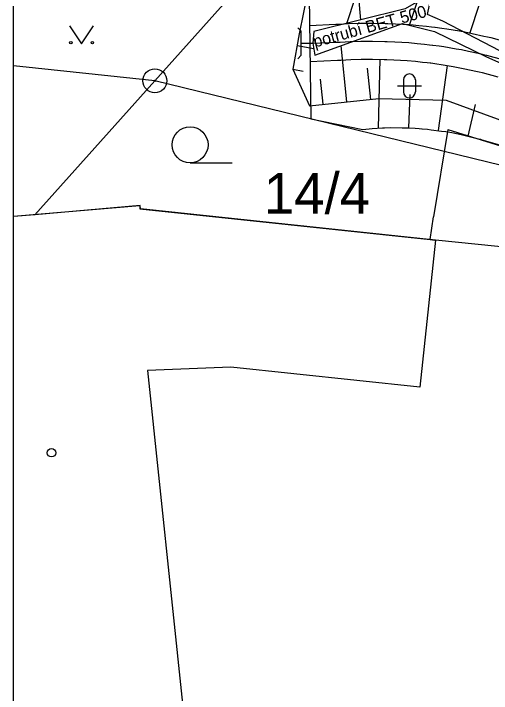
# Model space of a CAD drawing. Extents: x -564037 to -563722, y -1163561 to -1163412.
# Drawn here: x -564036.51 to -564016.6, y -1163474.68 to -1163446.37 of the extents above; entities that cross this region are included whole.
import ezdxf

# ---------------------------------------------------------------- set-up
doc = ezdxf.new("R2010")
doc.units = 0
for name, color, linetype in [('1', 7, 'Continuous'), ('Definiční body', 7, 'Continuous'), ('Hranice parcel', 7, 'Continuous'), ('Line', 7, 'Continuous'), ('Parcelní čísla', 7, 'Continuous'), ('Vnitřní kresba', 7, 'Continuous'), ('Vrstva 14', 7, 'Continuous'), ('Vrstva 20', 7, 'Continuous'), ('Vrstva 25', 7, 'Continuous'), ('Vrstva 41', 7, 'Continuous'), ('Vrstva 48', 7, 'Continuous'), ('Značky bodu BP', 7, 'Continuous'), ('Značky budov', 7, 'Continuous'), ('Značky kultur', 7, 'Continuous')]:
    doc.layers.add(name, color=color, linetype=linetype)

msp = doc.modelspace()

# ---------------------------------------------------------------- linework, layer by layer
for points in [[(-564024.219, -1163443.623), (-564024.118, -1163450.759), (-564021.959, -1163451.195), (-564021.563, -1163451.158), (-564021.141, -1163451.131), (-564021.053, -1163451.127), (-564020.798, -1163451.118), (-564020.319, -1163451.123), (-564020.03, -1163451.134), (-564019.77, -1163451.149), (-564019.605, -1163451.16), (-564019.496, -1163451.169), (-564019.485, -1163451.17), (-564019.482, -1163451.17), (-564019.263, -1163451.191), (-564019.103, -1163451.208), (-564018.675, -1163451.262), (-564018.499, -1163451.288), (-564018.254, -1163451.33), (-564017.862, -1163451.409), (-564017.742, -1163451.435), (-564017.633, -1163451.46), (-564017.074, -1163451.6), (-564017.058, -1163451.604), (-564016.993, -1163451.622), (-564016.265, -1163451.842)], [(-564024.173, -1163446.865), (-564023.075, -1163446.816), (-564022.934, -1163446.81), (-564022.523, -1163446.791), (-564022.059, -1163446.776), (-564021.555, -1163446.77), (-564021.021, -1163446.778), (-564020.91, -1163446.782), (-564020.588, -1163446.795), (-564019.985, -1163446.833), (-564019.623, -1163446.864), (-564019.297, -1163446.898), (-564019.09, -1163446.922), (-564018.953, -1163446.939), (-564018.939, -1163446.941), (-564018.937, -1163446.941), (-564018.662, -1163446.978), (-564018.462, -1163447.008), (-564017.928, -1163447.096), (-564017.708, -1163447.137), (-564017.402, -1163447.198), (-564016.912, -1163447.305), (-564016.761, -1163447.341), (-564016.625, -1163447.374), (-564015.927, -1163447.559)], [(-564024.04, -1163447.61), (-564023.041, -1163447.565), (-564022.901, -1163447.559), (-564022.489, -1163447.54), (-564022.042, -1163447.525), (-564021.557, -1163447.52), (-564021.042, -1163447.528), (-564020.935, -1163447.531), (-564020.624, -1163447.544), (-564020.043, -1163447.58), (-564019.694, -1163447.611), (-564019.38, -1163447.643), (-564019.18, -1163447.666), (-564019.049, -1163447.683), (-564019.035, -1163447.685), (-564019.033, -1163447.685), (-564018.768, -1163447.721), (-564018.575, -1163447.749), (-564018.06, -1163447.835), (-564017.848, -1163447.874), (-564017.553, -1163447.932), (-564017.081, -1163448.036), (-564016.936, -1163448.07), (-564016.805, -1163448.102), (-564016.131, -1163448.28)], [(-564024.152, -1163448.366), (-564023.007, -1163448.314), (-564022.867, -1163448.308), (-564022.456, -1163448.29), (-564022.025, -1163448.275), (-564021.558, -1163448.27), (-564021.063, -1163448.278), (-564020.96, -1163448.281), (-564020.661, -1163448.293), (-564020.102, -1163448.328), (-564019.765, -1163448.357), (-564019.463, -1163448.388), (-564019.271, -1163448.411), (-564019.144, -1163448.427), (-564019.131, -1163448.428), (-564019.129, -1163448.429), (-564018.874, -1163448.463), (-564018.688, -1163448.491), (-564018.193, -1163448.573), (-564017.988, -1163448.611), (-564017.705, -1163448.667), (-564017.25, -1163448.766), (-564017.111, -1163448.799), (-564016.984, -1163448.83), (-564016.336, -1163449.002)]]:
    msp.add_lwpolyline(points)
at = {"layer": '1'}
msp.add_lwpolyline([(-564036.505, -1163412.494), (-563721.505, -1163412.494), (-563721.505, -1163560.994), (-564036.505, -1163560.994)], close=True, dxfattribs=at)
at = {"layer": 'Definiční body'}
msp.add_lwpolyline([(-564018.41, -1163451.2), (-564019.01, -1163454.84)], dxfattribs=at)
at = {"layer": 'Hranice parcel'}
for p, q in [((-564030.62, -1163449.17), (-564025.34, -1163443.25)), ((-564035.62, -1163454.75), (-564030.62, -1163449.17)), ((-564035.62, -1163454.75), (-564036.505, -1163454.828))]:
    msp.add_line(p, q, dxfattribs=at)
for points in [[(-564030.62, -1163449.17), (-564036.505, -1163448.55)], [(-563988.32, -1163461.72), (-564001.74, -1163456.23), (-564030.62, -1163449.17)], [(-564018.93, -1163455.81), (-564031.22, -1163454.5), (-564031.23, -1163454.37), (-564035.62, -1163454.75)], [(-563996.99, -1163459.6), (-564013.06, -1163456.4), (-564018.93, -1163455.81)]]:
    msp.add_lwpolyline(points, dxfattribs=at)
at = {"layer": 'Line'}
for p, q in [((-564021.847, -1163444.413), (-564022.64, -1163446.796)), ((-564019.475, -1163445.202), (-564020.017, -1163446.831)), ((-564017.103, -1163445.992), (-564017.498, -1163447.179)), ((-564021.301, -1163451.142), (-564021.238, -1163448.275)), ((-564018.807, -1163451.245), (-564018.434, -1163448.533)), ((-564019.994, -1163449.738), (-564020.052, -1163451.133)), ((-564017.273, -1163450.154), (-564017.579, -1163451.474))]:
    msp.add_line(p, q, dxfattribs=at)
at = {"layer": 'Vnitřní kresba'}
msp.add_line((-564030.92, -1163461.24), (-564029.42, -1163475.59), dxfattribs=at)
msp.add_lwpolyline([(-564018.93, -1163455.81), (-564019.58, -1163461.93), (-564027.45, -1163461.09), (-564030.92, -1163461.24)], dxfattribs=at)
at = {"layer": 'Vrstva 14'}
for points in [[(-564007.48, -1163451.56), (-564015.37, -1163448.38), (-564016.56, -1163447.76), (-564018.62, -1163446.69), (-564019.26, -1163446.41), (-564019.18, -1163446.01), (-564017.7, -1163444.08)], [(-564018.38, -1163444.22), (-564019.25, -1163445.51), (-564019.73, -1163445.91), (-564020.19, -1163446.17), (-564024, -1163447.12)], [(-564021.14, -1163444.81), (-564023.19, -1163444.97), (-564024.24, -1163445.43), (-564024.61, -1163447.21), (-564024.87, -1163448.69), (-564024.18, -1163450.21), (-564021.29, -1163449.91), (-564018.48, -1163449.97), (-564014.8, -1163451.33), (-564012.14, -1163452.66), (-564006.89, -1163454.96)], [(-564023.95, -1163448.11), (-564020.3, -1163446.78), (-564018.97, -1163447.12), (-564016.8, -1163448.17), (-564015.46, -1163448.77), (-564007.72, -1163452.04)], [(-564024, -1163447.12), (-564024.04, -1163447.61), (-564023.95, -1163448.11)], [(-564018.41, -1163451.2), (-564015.23, -1163452.19), (-564012.52, -1163453.4), (-564007.28, -1163455.88), (-563999.25, -1163459.72), (-563994.12, -1163462.21), (-563988.58, -1163464.9), (-563990.48, -1163473.96), (-563991.73, -1163479.99), (-563994.29, -1163491.84), (-564004.63, -1163491.62)], [(-564019.15, -1163455.78), (-564019.01, -1163454.84)]]:
    msp.add_lwpolyline(points, dxfattribs=at)
at = {"layer": 'Vrstva 20'}
for p, q in [((-564024.669, -1163446.969), (-564024.528, -1163447.11)), ((-564024.528, -1163448.11), (-564024.528, -1163447.11)), ((-564024.528, -1163447.61), (-564024.04, -1163447.61)), ((-564024.669, -1163448.251), (-564024.528, -1163448.11))]:
    msp.add_line(p, q, dxfattribs=at)
at = {"layer": 'Vrstva 25'}
for p, q in [((-564020.266, -1163449.136), (-564020.266, -1163449.636)), ((-564019.766, -1163449.136), (-564019.766, -1163449.636)), ((-564020.516, -1163449.386), (-564019.516, -1163449.386))]:
    msp.add_line(p, q, dxfattribs=at)
msp.add_lwpolyline([(-564034.17, -1163446.88), (-564033.67, -1163447.63), (-564033.17, -1163446.88)], dxfattribs=at)
for centre in [(-564034.12, -1163447.58), (-564033.221, -1163447.58)]:
    msp.add_circle(centre, 0.05, dxfattribs=at)
for centre, start, end in [((-564020.016, -1163449.136), 0, 180), ((-564020.016, -1163449.636), 180, 0)]:
    msp.add_arc(centre, 0.25, start, end, dxfattribs=at)
at = {"layer": 'Vrstva 48'}
for p, q in [((-564022.193, -1163444.892), (-564022.057, -1163446.636)), ((-564024.697, -1163447.705), (-564024, -1163447.828)), ((-564022.615, -1163450.047), (-564022.857, -1163447.712)), ((-564021.621, -1163449.944), (-564021.754, -1163448.651)), ((-564024.87, -1163448.69), (-564024.435, -1163448.766)), ((-564023.61, -1163450.15), (-564023.718, -1163449.107))]:
    msp.add_line(p, q, dxfattribs=at)
at = {"layer": 'Značky bodu BP'}
for radius in [0.5, 0.0303]:
    msp.add_circle((-564030.62, -1163449.17), radius, dxfattribs=at)
at = {"layer": 'Značky budov'}
msp.add_lwpolyline([(-564036.505, -1163454.802), (-564031.25, -1163454.37), (-564031.24, -1163454.5), (-564019.15, -1163455.78), (-564018.96, -1163455.8)], dxfattribs=at)
msp.add_circle((-564034.927, -1163464.659), 0.175, dxfattribs=at)
at = {"layer": 'Značky kultur'}
msp.add_line((-564029.153, -1163452.59), (-564027.403, -1163452.59), dxfattribs=at)
msp.add_circle((-564029.153, -1163451.84), 0.75, dxfattribs=at)

# ---------------------------------------------------------------- texts
at = {"layer": 'Parcelní čísla'}
msp.add_text('14/4', height=1.7, dxfattribs=at).set_placement((-564026.079, -1163454.71))
at = {"layer": 'Vrstva 41'}
msp.add_text('potrubí BET 500', height=0.5, rotation=15.4129, dxfattribs=at).set_placement((-564023.95, -1163447.79))

doc.saveas('drawing.dxf')
